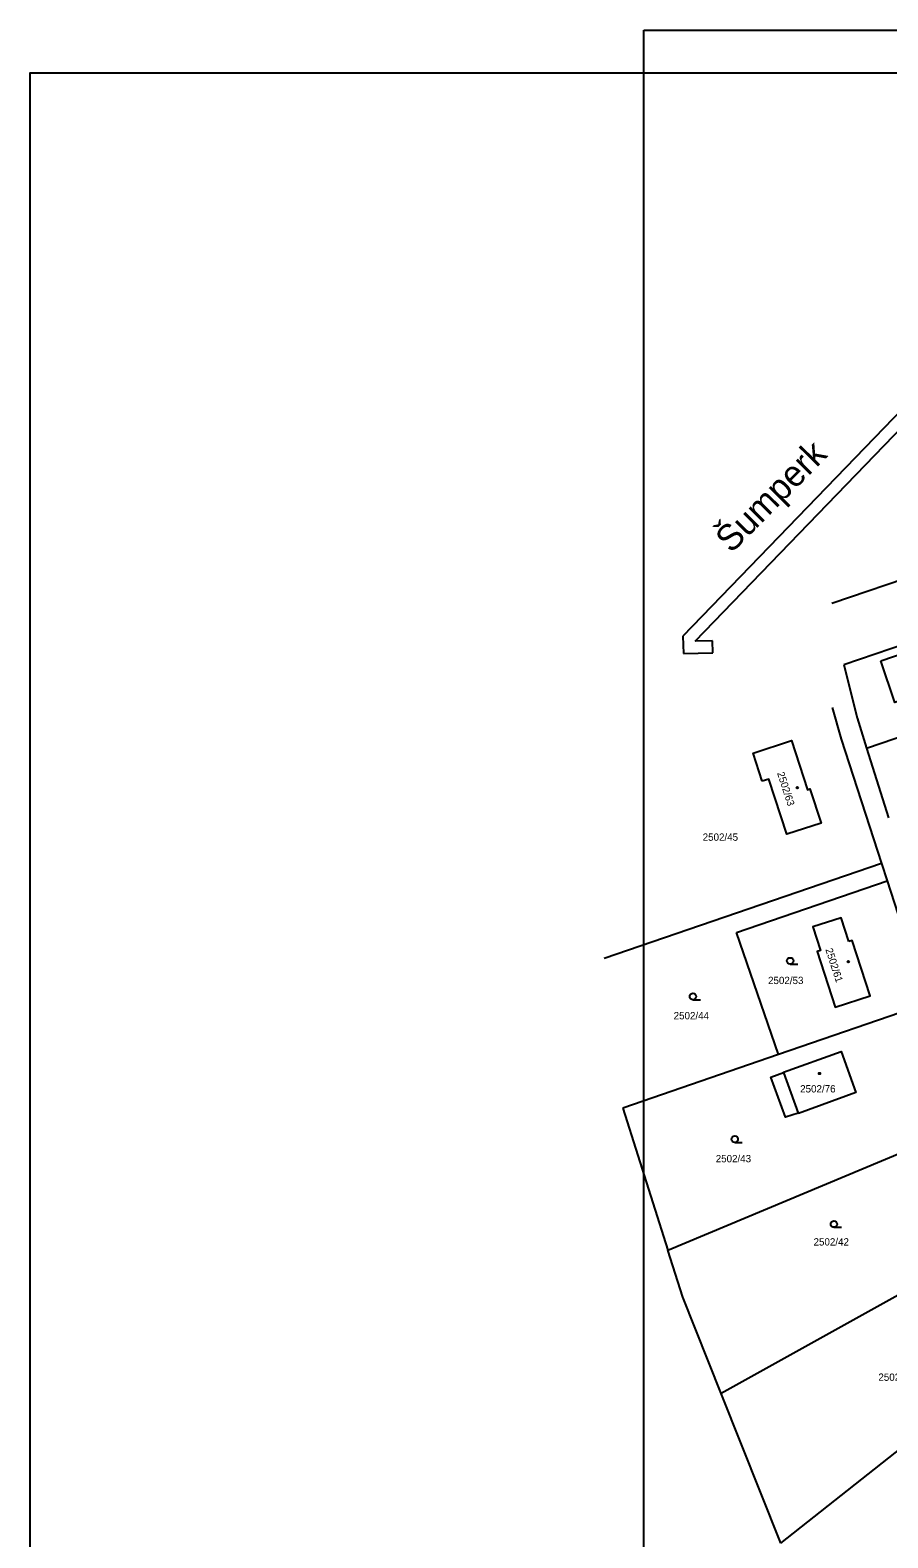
# Model space of a CAD drawing. Extents: x -558500 to -557517, y -1073973 to -1073051.
# Drawn here: x -558500 to -558300.8, y -1073540.5 to -1073190.1 of the extents above; entities that cross this region are included whole.
import ezdxf

# ---------------------------------------------------------------- set-up
doc = ezdxf.new("R2010")
doc.units = 0
for name, color, linetype in [('Default', 7, 'Continuous'), ('Hranice parcel', 7, 'Continuous'), ('Parcelní čísla', 7, 'Continuous'), ('Vnitřní kresba', 7, 'Continuous'), ('Vrstva 1', 7, 'Continuous'), ('Značky budov', 7, 'Continuous'), ('Značky kultur', 7, 'Continuous')]:
    doc.layers.add(name, color=color, linetype=linetype)

msp = doc.modelspace()

# ---------------------------------------------------------------- linework, layer by layer
at = {"layer": 'Default'}
msp.add_lwpolyline([(-557909.21, -1073700), (-558500, -1073700), (-558500, -1073200), (-557800, -1073200), (-557800, -1073567.6)], dxfattribs=at)
at = {"layer": 'Hranice parcel'}
for p, q in [((-558313.8, -1073323.28), (-558248.97, -1073301.04)), ((-558245.27, -1073315.03), (-558311.02, -1073337.58)), ((-558305.76, -1073356.92), (-558240.15, -1073334.41)), ((-558305.76, -1073356.92), (-558300.65, -1073373.14)), ((-558302.31, -1073383.75), (-558366.72, -1073405.84)), ((-558302.31, -1073383.75), (-558301.02, -1073387.75)), ((-558335.97, -1073399.79), (-558301.02, -1073387.75)), ((-558326.19, -1073428.15), (-558335.97, -1073399.79)), ((-558291.74, -1073416.28), (-558326.19, -1073428.15)), ((-558326.19, -1073428.15), (-558362.39, -1073440.63)), ((-558362.39, -1073440.63), (-558351.92, -1073473.58)), ((-558351.92, -1073473.58), (-558280.07, -1073443.5)), ((-558269.87, -1073468.15), (-558339.52, -1073506.95)), ((-558325.69, -1073541.72), (-558259.89, -1073489.61)), ((-558325.69, -1073541.72), (-558339.52, -1073506.95))]:
    msp.add_line(p, q, dxfattribs=at)
for points in [[(-558302.49, -1073336.69), (-558282.13, -1073329.71), (-558282.06, -1073329.92), (-558279.49, -1073329.04), (-558277.55, -1073334.7), (-558280.12, -1073335.56), (-558280.04, -1073335.79), (-558289.36, -1073338.99), (-558288.15, -1073342.54), (-558299.21, -1073346.34), (-558302.49, -1073336.69)], [(-558311.02, -1073337.58), (-558307.96, -1073349.92), (-558305.76, -1073356.92)], [(-558313.78, -1073347.52), (-558311.65, -1073354.86), (-558302.31, -1073383.75)], [(-558329.99, -1073364.63), (-558332.12, -1073358.09), (-558323.21, -1073355.2), (-558319.51, -1073366.6), (-558318.91, -1073366.43), (-558316.33, -1073374.39), (-558324.28, -1073376.97), (-558328.43, -1073364.14), (-558329.99, -1073364.63)], [(-558301.02, -1073387.75), (-558291.95, -1073415.8), (-558291.74, -1073416.28)], [(-558309.9, -1073401.85), (-558311.67, -1073396.36), (-558318.22, -1073398.44), (-558316.44, -1073403.96), (-558317.23, -1073404.23), (-558313.09, -1073417.12), (-558304.96, -1073414.53), (-558309.1, -1073401.61), (-558309.9, -1073401.85)], [(-558321.61, -1073441.85), (-558321.65, -1073441.75), (-558324.57, -1073442.7), (-558327.97, -1073433.39), (-558325.04, -1073432.33), (-558325.07, -1073432.22), (-558311.66, -1073427.42), (-558308.26, -1073436.97), (-558321.61, -1073441.85)], [(-558339.52, -1073506.95), (-558348.44, -1073484.55), (-558351.92, -1073473.58)]]:
    msp.add_lwpolyline(points, dxfattribs=at)
at = {"layer": 'Vnitřní kresba'}
msp.add_line((-558325.04, -1073432.33), (-558321.65, -1073441.75), dxfattribs=at)
at = {"layer": 'Vrstva 1'}
for p, q in [((-558357.53, -1073784.09), (-558357.53, -1073190.09)), ((-558357.53, -1073190.09), (-557516.53, -1073190.09)), ((-558280.86, -1073260.92), (-558348.4, -1073330.92)), ((-558345.54, -1073332.05), (-558278.82, -1073262.89)), ((-558348.4, -1073330.92), (-558348.32, -1073334.93)), ((-558348.32, -1073334.93), (-558341.48, -1073334.81)), ((-558341.53, -1073331.97), (-558345.54, -1073332.05)), ((-558341.48, -1073334.81), (-558341.53, -1073331.97))]:
    msp.add_line(p, q, dxfattribs=at)
at = {"layer": 'Značky budov'}
for centre in [(-558321.85, -1073366.12), (-558310.02, -1073406.56), (-558316.7, -1073432.55)]:
    msp.add_circle(centre, 0.175, dxfattribs=at)
at = {"layer": 'Značky kultur'}
for p, q in [((-558323.52, -1073407.14), (-558321.77, -1073407.14)), ((-558346.09, -1073415.41), (-558344.34, -1073415.41)), ((-558336.38, -1073448.57), (-558334.63, -1073448.57)), ((-558313.35, -1073468.3), (-558311.6, -1073468.3))]:
    msp.add_line(p, q, dxfattribs=at)
for centre in [(-558323.52, -1073406.39), (-558346.09, -1073414.66), (-558336.38, -1073447.82), (-558313.35, -1073467.55)]:
    msp.add_circle(centre, 0.75, dxfattribs=at)

# ---------------------------------------------------------------- texts
at = {"layer": 'Parcelní čísla'}
for s, p in [('2502/63', (-558326.57, -1073362.74)), ('2502/61', (-558315.36, -1073403.73))]:
    msp.add_text(s, height=1.7, rotation=288, dxfattribs=at).set_placement(p)
for s, p in [('2502/45', (-558343.83, -1073378.47)), ('2502/53', (-558328.65, -1073411.77)), ('2502/44', (-558350.57, -1073419.96)), ('2502/76', (-558321.19, -1073436.96)), ('2502/43', (-558340.8, -1073453.18)), ('2502/42', (-558318.08, -1073472.53)), ('2502/41', (-558303.03, -1073503.97))]:
    msp.add_text(s, height=1.7, dxfattribs=at).set_placement(p)
at = {"layer": 'Vrstva 1'}
msp.add_text('Šumperk', height=6, rotation=45.2335, dxfattribs=at).set_placement((-558337.2, -1073311.84))

doc.saveas('drawing.dxf')
